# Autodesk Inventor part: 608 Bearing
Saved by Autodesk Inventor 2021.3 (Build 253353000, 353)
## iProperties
Created: 2023-01
Part Number: 608 Bearing
Material: Generic
Document SubType Name: Modeling
Designer: AdminForWorker
Density: 1 g/cm^3
Appearance: Default
Title: 608 Bearing
Author: AdminForWorker
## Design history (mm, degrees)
feature "608 Bearing"
body "Solid1"
